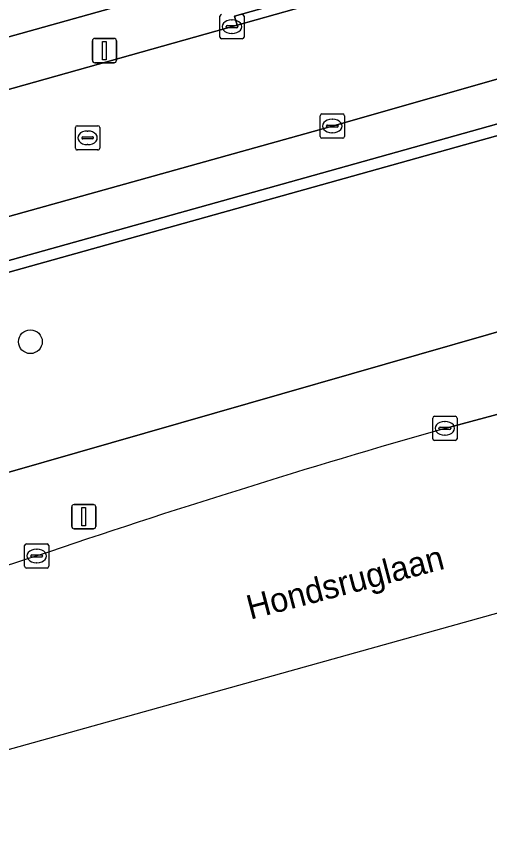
# Model space of a CAD drawing. Extents: x 159626 to 160723, y 388173 to 389416.
# Drawn here: x 159987.78 to 160007.27, y 388255.14 to 388288.7 of the extents above; entities that cross this region are included whole.
import ezdxf

# ---------------------------------------------------------------- set-up
doc = ezdxf.new("R2010")
doc.units = 0
for name, color, linetype in [('IMGEO_Boom', 7, 'Continuous'), ('IMGEO_Erf', 7, 'Continuous'), ('IMGEO_Groenvoorziening', 7, 'Continuous'), ('IMGEO_Kolk', 7, 'Continuous'), ('IMGEO_Lichtmast', 7, 'Continuous'), ('IMGEO_Openbare_ruimte_label', 7, 'Continuous'), ('IMGEO_Parkeervlak_open', 7, 'Continuous'), ('IMGEO_Rijbaan_lokaal_open', 7, 'Continuous'), ('IMGEO_Rijbaan_regionaal_gesloten', 7, 'Continuous'), ('IMGEO_Rioolput', 7, 'Continuous'), ('IMGEO_Voetpad_open', 7, 'Continuous')]:
    doc.layers.add(name, color=color, linetype=linetype)

msp = doc.modelspace()

# ---------------------------------------------------------------- linework, layer by layer
at = {"layer": 'IMGEO_Boom'}
msp.add_circle((159988.358, 388275.309), 0.489, dxfattribs=at)
at = {"layer": 'IMGEO_Erf'}
msp.add_lwpolyline([(159893.644, 388261.656), (159940.482, 388274.742), (160000, 388291.371), (160013.03, 388294.925), (160013.985, 388295.31)], dxfattribs=at)
at = {"layer": 'IMGEO_Groenvoorziening'}
for points in [[(160020.117, 388276.986), (160019.381, 388280.018), (160019.313, 388280.785), (160019.315, 388281.813), (160019.579, 388287.147), (160016.393, 388286.257), (160000, 388281.676), (159943.07, 388265.766), (159923.296, 388260.24), (159886.729, 388250), (159844.944, 388238.299), (159842.813, 388239.959), (159842.555, 388239.919), (159842.41, 388239.878), (159841.82, 388239.721)], [(160005.426, 388271.742), (160015.167, 388274.35), (160014.256, 388277.622), (159986.028, 388269.523), (159986.438, 388268.086), (159971.092, 388263.372), (159969.703, 388262.967), (159962.179, 388260.771), (159945.882, 388256.016), (159926.651, 388250.405), (159925.196, 388250), (159916.577, 388248.216), (159892.687, 388240.775), (159833.979, 388224.356)], [(159945.882, 388256.016), (159962.179, 388260.771), (159961.673, 388262.536), (159970.684, 388265.121), (159986.028, 388269.523), (160014.256, 388277.622), (160015.167, 388274.35), (160015.516, 388274.443)]]:
    msp.add_lwpolyline(points, dxfattribs=at)
for centre, radius, start, end in [((160105.803, 387921.072), 364.753, 105.97341, 108.73968), ((160088.816, 387951.623), 330.424, 107.65221, 110.55838)]:
    msp.add_arc(centre, radius, start, end, dxfattribs=at)
at = {"layer": 'IMGEO_Kolk'}
for p, q in [((159996.158, 388287.852), (159996.158, 388288.704)), ((159996.646, 388288.558), (159996.671, 388288.558)), ((159997.159, 388288.704), (159997.159, 388287.852)), ((159996.417, 388288.272), (159996.417, 388288.284)), ((159996.855, 388288.235), (159996.457, 388288.235)), ((159996.46, 388288.321), (159996.858, 388288.321)), ((159996.901, 388288.284), (159996.901, 388288.272)), ((159996.669, 388287.998), (159996.644, 388287.998)), ((159997.085, 388287.778), (159996.233, 388287.778)), ((160000.291, 388283.76), (160000.291, 388284.612)), ((160000.366, 388284.686), (160001.218, 388284.686)), ((160001.292, 388284.612), (160001.292, 388283.76)), ((160000.55, 388284.18), (160000.55, 388284.192)), ((160000.593, 388284.229), (160000.991, 388284.229)), ((160000.779, 388284.466), (160000.804, 388284.466)), ((160001.034, 388284.192), (160001.034, 388284.18)), ((160000.988, 388284.143), (160000.59, 388284.143)), ((160000.802, 388283.906), (160000.777, 388283.906)), ((160001.218, 388283.686), (160000.366, 388283.686)), ((160004.925, 388271.316), (160004.925, 388272.168)), ((160005, 388272.242), (160005.852, 388272.242)), ((160005.926, 388272.168), (160005.926, 388271.316)), ((160005.184, 388271.736), (160005.184, 388271.748)), ((160005.227, 388271.785), (160005.625, 388271.785)), ((160005.413, 388272.022), (160005.438, 388272.022)), ((160005.668, 388271.748), (160005.668, 388271.736)), ((160005.622, 388271.699), (160005.224, 388271.699)), ((160005.436, 388271.462), (160005.411, 388271.462)), ((160005.852, 388271.242), (160005, 388271.242)), ((159988.118, 388266.063), (159988.118, 388266.915)), ((159988.193, 388266.989), (159989.045, 388266.989)), ((159988.606, 388266.769), (159988.631, 388266.769)), ((159989.119, 388266.915), (159989.119, 388266.063)), ((159988.377, 388266.483), (159988.377, 388266.495)), ((159988.815, 388266.446), (159988.417, 388266.446)), ((159988.42, 388266.532), (159988.818, 388266.532)), ((159988.861, 388266.495), (159988.861, 388266.483)), ((159988.629, 388266.209), (159988.604, 388266.209)), ((159989.045, 388265.989), (159988.193, 388265.989))]:
    msp.add_line(p, q, dxfattribs=at)
for points in [[(159996.158, 388287.852), (159996.158, 388288.704)], [(159997.159, 388288.704), (159997.159, 388287.852)], [(159997.085, 388287.778), (159996.233, 388287.778)], [(160000.291, 388283.76), (160000.291, 388284.612)], [(160000.366, 388284.686), (160001.218, 388284.686)], [(160001.292, 388284.612), (160001.292, 388283.76)], [(160001.218, 388283.686), (160000.366, 388283.686)], [(160004.925, 388271.316), (160004.925, 388272.168)], [(160005, 388272.242), (160005.852, 388272.242)], [(160005.926, 388272.168), (160005.926, 388271.316)], [(160005.852, 388271.242), (160005, 388271.242)], [(159988.118, 388266.063), (159988.118, 388266.915)], [(159988.193, 388266.989), (159989.045, 388266.989)], [(159989.119, 388266.915), (159989.119, 388266.063)], [(159989.045, 388265.989), (159988.193, 388265.989)]]:
    msp.add_lwpolyline(points, dxfattribs=at)
for centre, radius, start, end in [((159996.235, 388288.702), 0.0765, 91.552, 178.448), ((159996.235, 388288.702), 0.0765, 91.552, 178.448), ((159997.083, 388288.702), 0.0765, 1.552, 88.448), ((159997.083, 388288.702), 0.0765, 1.552, 88.448), ((159996.457, 388288.281), 0.0403, 85.8775, 175.7526), ((159996.454, 388288.271), 0.0366, 178.938, 274.7102), ((159996.858, 388288.278), 0.043, 264.8664, 352.4533), ((159996.862, 388288.283), 0.0386, 1.7309, 96.639), ((159996.235, 388287.854), 0.0765, 181.552, 268.448), ((159996.235, 388287.854), 0.0765, 181.552, 268.448), ((159997.083, 388287.854), 0.0765, 271.552, 358.448), ((159997.083, 388287.854), 0.0765, 271.552, 358.448), ((160000.368, 388284.61), 0.0765, 91.552, 178.448), ((160000.368, 388284.61), 0.0765, 91.552, 178.448), ((160001.216, 388284.61), 0.0765, 1.552, 88.448), ((160001.216, 388284.61), 0.0765, 1.552, 88.448), ((160000.59, 388284.189), 0.0403, 85.8775, 175.7526), ((160000.587, 388284.179), 0.0366, 178.938, 274.7102), ((160000.991, 388284.186), 0.043, 264.8664, 352.4533), ((160000.995, 388284.191), 0.0386, 1.7309, 96.639), ((160000.368, 388283.762), 0.0765, 181.552, 268.448), ((160000.368, 388283.762), 0.0765, 181.552, 268.448), ((160001.216, 388283.762), 0.0765, 271.552, 358.448), ((160001.216, 388283.762), 0.0765, 271.552, 358.448), ((160005.002, 388272.166), 0.0765, 91.552, 178.448), ((160005.002, 388272.166), 0.0765, 91.552, 178.448), ((160005.85, 388272.166), 0.0765, 1.552, 88.448), ((160005.85, 388272.166), 0.0765, 1.552, 88.448), ((160005.224, 388271.745), 0.0403, 85.8775, 175.7526), ((160005.221, 388271.735), 0.0366, 178.938, 274.7102), ((160005.625, 388271.742), 0.043, 264.8664, 352.4533), ((160005.629, 388271.747), 0.0386, 1.7309, 96.639), ((160005.002, 388271.318), 0.0765, 181.552, 268.448), ((160005.002, 388271.318), 0.0765, 181.552, 268.448), ((160005.85, 388271.318), 0.0765, 271.552, 358.448), ((160005.85, 388271.318), 0.0765, 271.552, 358.448), ((159988.195, 388266.913), 0.0765, 91.552, 178.448), ((159988.195, 388266.913), 0.0765, 91.552, 178.448), ((159989.043, 388266.913), 0.0765, 1.552, 88.448), ((159989.043, 388266.913), 0.0765, 1.552, 88.448), ((159988.417, 388266.492), 0.0403, 85.8775, 175.7526), ((159988.414, 388266.482), 0.0366, 178.938, 274.7102), ((159988.818, 388266.489), 0.043, 264.8664, 352.4533), ((159988.822, 388266.494), 0.0386, 1.7309, 96.639), ((159988.195, 388266.065), 0.0765, 181.552, 268.448), ((159988.195, 388266.065), 0.0765, 181.552, 268.448), ((159989.043, 388266.065), 0.0765, 271.552, 358.448), ((159989.043, 388266.065), 0.0765, 271.552, 358.448)]:
    msp.add_arc(centre, radius, start, end, dxfattribs=at)
for centre, major_axis, ratio, start_param, end_param in [((159996.645, 388288.278), (-0.387, 0.002), 0.722429, 4.712389, 7.853982), ((159996.67, 388288.278), (-0.39, 0.002), 0.717154, 1.570796, 4.712389), ((160000.778, 388284.186), (-0.387, 0.002), 0.722429, 4.712389, 7.853982), ((160000.803, 388284.186), (-0.39, 0.002), 0.717154, 1.570796, 4.712389), ((160005.412, 388271.742), (-0.387, 0.002), 0.722429, 4.712389, 7.853982), ((160005.437, 388271.742), (-0.39, 0.002), 0.717154, 1.570796, 4.712389), ((159988.605, 388266.489), (-0.387, 0.002), 0.722429, 4.712389, 7.853982), ((159988.63, 388266.489), (-0.39, 0.002), 0.717154, 1.570796, 4.712389)]:
    msp.add_ellipse(centre, major_axis=major_axis, ratio=ratio, start_param=start_param, end_param=end_param, dxfattribs=at)
at = {"layer": 'IMGEO_Lichtmast'}
for p, q in [((159990.913, 388286.892), (159990.913, 388287.692)), ((159990.913, 388287.692), (159990.913, 388286.892)), ((159991.013, 388287.792), (159991.803, 388287.792)), ((159991.803, 388287.792), (159991.013, 388287.792)), ((159991.903, 388287.692), (159991.903, 388286.892)), ((159991.903, 388286.892), (159991.903, 388287.692)), ((159991.803, 388286.792), (159991.013, 388286.792)), ((159991.013, 388286.792), (159991.803, 388286.792)), ((159990.061, 388267.708), (159990.061, 388268.508)), ((159990.061, 388268.508), (159990.061, 388267.708)), ((159990.161, 388268.608), (159990.951, 388268.608)), ((159990.951, 388268.608), (159990.161, 388268.608)), ((159991.051, 388268.508), (159991.051, 388267.708)), ((159991.051, 388267.708), (159991.051, 388268.508)), ((159990.951, 388267.608), (159990.161, 388267.608)), ((159990.161, 388267.608), (159990.951, 388267.608))]:
    msp.add_line(p, q, dxfattribs=at)
for points in [[(159991.333, 388287.667), (159991.483, 388287.667), (159991.483, 388286.917), (159991.333, 388286.917), (159991.333, 388287.667)], [(159990.481, 388268.483), (159990.631, 388268.483), (159990.631, 388267.733), (159990.481, 388267.733), (159990.481, 388268.483)]]:
    msp.add_lwpolyline(points, dxfattribs=at)
for centre, start, end in [((159991.013, 388287.692), 90, 180), ((159991.013, 388287.692), 90, 180), ((159991.803, 388287.692), 0, 90), ((159991.803, 388287.692), 360, 90), ((159991.013, 388286.892), 180, 270), ((159991.013, 388286.892), 180, 270), ((159991.803, 388286.892), 270, 0), ((159991.803, 388286.892), 270, 0), ((159990.161, 388268.508), 90, 180), ((159990.161, 388268.508), 90, 180), ((159990.951, 388268.508), 0, 90), ((159990.951, 388268.508), 360, 90), ((159990.161, 388267.708), 180, 270), ((159990.161, 388267.708), 180, 270), ((159990.951, 388267.708), 270, 0), ((159990.951, 388267.708), 270, 0)]:
    msp.add_arc(centre, 0.1, start, end, dxfattribs=at)
at = {"layer": 'IMGEO_Parkeervlak_open'}
for points in [[(160015.391, 388288.325), (160013.445, 388287.791), (160000.787, 388284.187), (160000, 388283.967), (159961.24, 388273.152), (159942.469, 388267.934), (159942.447, 388267.928), (159922.721, 388262.424), (159901.075, 388256.353), (159883.393, 388251.41), (159878.37, 388250), (159863.481, 388245.821), (159848.736, 388241.658), (159842.813, 388239.959)], [(159845.459, 388238.901), (159885.039, 388250), (159923.193, 388260.699), (159942.941, 388266.216), (160000, 388282.156), (160013.39, 388285.897)]]:
    msp.add_lwpolyline(points, dxfattribs=at)
at = {"layer": 'IMGEO_Rijbaan_lokaal_open'}
msp.add_lwpolyline([(159942.447, 388267.928), (159942.469, 388267.934), (159961.24, 388273.152), (160000, 388283.967), (160000.787, 388284.187), (160013.445, 388287.791), (160015.391, 388288.325), (160015.802, 388288.44), (160014.596, 388292.994), (160006.167, 388290.779), (160003.456, 388290.183), (160000, 388289.214), (159996.875, 388288.337), (159986.316, 388285.375), (159979.756, 388283.534), (159968.71, 388280.435), (159965.037, 388279.403), (159941.069, 388272.705), (159898.585, 388260.761)], dxfattribs=at)
at = {"layer": 'IMGEO_Rijbaan_regionaal_gesloten'}
for points in [[(160015.516, 388274.443), (160015.167, 388274.35), (160005.426, 388271.742)], [(159698.928, 388178.017), (159861.579, 388223.398), (160022.114, 388268.189), (160021.708, 388269.57), (160016.34, 388268.102)]]:
    msp.add_lwpolyline(points, dxfattribs=at)
for centre, radius, start, end in [((160105.803, 387921.072), 364.753, 105.97341, 108.73968), ((160088.816, 387951.623), 330.424, 107.65221, 110.55838)]:
    msp.add_arc(centre, radius, start, end, dxfattribs=at)
at = {"layer": 'IMGEO_Rioolput'}
for p, q in [((159990.288, 388284.201), (159991.14, 388284.201)), ((159990.213, 388283.275), (159990.213, 388284.127)), ((159990.701, 388283.981), (159990.726, 388283.981)), ((159991.214, 388284.127), (159991.214, 388283.275)), ((159990.472, 388283.695), (159990.472, 388283.707)), ((159990.91, 388283.658), (159990.512, 388283.658)), ((159990.515, 388283.744), (159990.913, 388283.744)), ((159990.956, 388283.707), (159990.956, 388283.695)), ((159991.14, 388283.201), (159990.288, 388283.201)), ((159990.724, 388283.421), (159990.699, 388283.421))]:
    msp.add_line(p, q, dxfattribs=at)
for points in [[(159990.288, 388284.201), (159991.14, 388284.201)], [(159990.213, 388283.275), (159990.213, 388284.127)], [(159991.214, 388284.127), (159991.214, 388283.275)], [(159991.14, 388283.201), (159990.288, 388283.201)]]:
    msp.add_lwpolyline(points, dxfattribs=at)
for centre, radius, start, end in [((159990.29, 388284.125), 0.0765, 91.552, 178.448), ((159990.29, 388284.125), 0.0765, 91.552, 178.448), ((159991.138, 388284.125), 0.0765, 1.552, 88.448), ((159991.138, 388284.125), 0.0765, 1.552, 88.448), ((159990.512, 388283.704), 0.0403, 85.8775, 175.7526), ((159990.509, 388283.694), 0.0366, 178.938, 274.7102), ((159990.913, 388283.701), 0.043, 264.8664, 352.4533), ((159990.917, 388283.706), 0.0386, 1.7309, 96.639), ((159990.29, 388283.277), 0.0765, 181.552, 268.448), ((159990.29, 388283.277), 0.0765, 181.552, 268.448), ((159991.138, 388283.277), 0.0765, 271.552, 358.448), ((159991.138, 388283.277), 0.0765, 271.552, 358.448)]:
    msp.add_arc(centre, radius, start, end, dxfattribs=at)
for centre, major_axis, ratio, start_param, end_param in [((159990.7, 388283.701), (-0.387, 0.002), 0.722429, 4.712389, 7.853982), ((159990.725, 388283.701), (-0.39, 0.002), 0.717154, 1.570796, 4.712389)]:
    msp.add_ellipse(centre, major_axis=major_axis, ratio=ratio, start_param=start_param, end_param=end_param, dxfattribs=at)
at = {"layer": 'IMGEO_Voetpad_open'}
for points in [[(160014.596, 388292.994), (160013.985, 388295.31), (160013.03, 388294.925), (160000, 388291.371), (159940.482, 388274.742), (159893.644, 388261.656), (159890.751, 388260.859), (159859.945, 388252.179), (159854.746, 388250.727), (159853.266, 388250.313), (159853.151, 388250.281), (159853.021, 388250.711), (159850.494, 388250), (159845.138, 388248.493), (159844.644, 388248.354), (159842.921, 388247.869), (159839.772, 388246.983), (159784.145, 388231.332), (159767.275, 388225.855), (159755.968, 388222.214)], [(159898.585, 388260.761), (159941.069, 388272.705), (159965.037, 388279.403), (159964.938, 388279.853), (159968.589, 388280.864), (159968.71, 388280.435), (159979.756, 388283.534), (159979.667, 388283.956), (159986.208, 388285.785), (159986.316, 388285.375), (159996.875, 388288.337), (159996.762, 388288.715), (160000, 388289.63), (160003.348, 388290.576), (160003.456, 388290.183), (160006.167, 388290.779), (160014.596, 388292.994)], [(159842.813, 388239.959), (159844.944, 388238.299), (159886.729, 388250), (159923.296, 388260.24), (159943.07, 388265.766), (160000, 388281.676), (160016.393, 388286.257), (160015.802, 388288.44)], [(160013.39, 388285.897), (160000, 388282.156), (159942.941, 388266.216), (159923.193, 388260.699), (159885.039, 388250), (159845.459, 388238.901)]]:
    msp.add_lwpolyline(points, dxfattribs=at)
msp.add_lwpolyline([(159996.875, 388288.337), (160000, 388289.214), (160003.456, 388290.183), (160003.348, 388290.576), (160000, 388289.63), (159996.762, 388288.715)], close=True, dxfattribs=at)

# ---------------------------------------------------------------- texts
at = {"layer": 'IMGEO_Openbare_ruimte_label'}
msp.add_text('Hondsruglaan', height=1, rotation=14.6619, dxfattribs=at).set_placement((159997.415, 388263.863))

doc.saveas('drawing.dxf')
